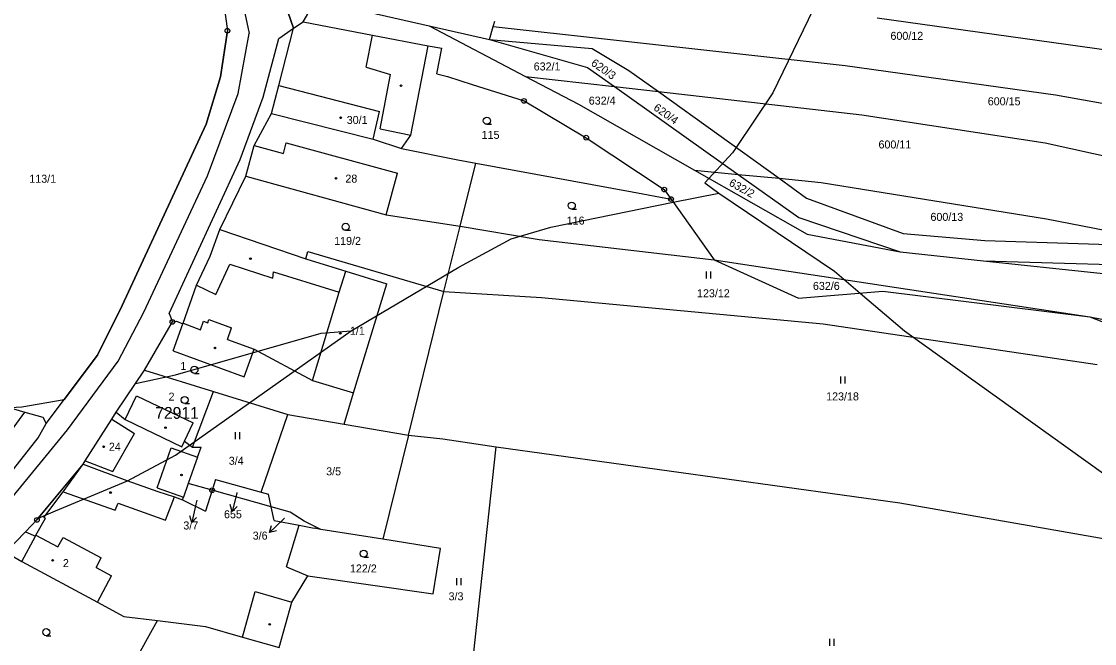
# Model space of a CAD drawing. Extents: x -743888 to -742027, y -1128394 to -1126768.
# Drawn here: x -742825.9 to -742597.9, y -1127325 to -1127193 of the extents above; entities that cross this region are included whole.
import ezdxf

# ---------------------------------------------------------------- set-up
doc = ezdxf.new("R2010")
doc.units = 0
for name, color, linetype in [('Vrstva 1', 7, 'Continuous'), ('Vrstva 16', 7, 'Continuous'), ('Vrstva 18', 7, 'Continuous'), ('Vrstva 19', 7, 'Continuous'), ('Vrstva 24', 7, 'Continuous'), ('Vrstva 25', 7, 'Continuous'), ('Vrstva 3', 7, 'Continuous'), ('Vrstva 37', 7, 'Continuous'), ('Vrstva 4', 7, 'Continuous'), ('Vrstva 52', 7, 'Continuous'), ('Vrstva 53', 7, 'Continuous'), ('Vrstva 6', 7, 'Continuous')]:
    doc.layers.add(name, color=color, linetype=linetype)

msp = doc.modelspace()

# ---------------------------------------------------------------- linework, layer by layer
at = {"layer": 'Vrstva 1'}
for p, q in [((-742743.69, -1127280.81), (-742749.15, -1127302.87)), ((-742788.48, -1127285.47), (-742790.45, -1127291.06)), ((-742790.45, -1127291.06), (-742791.47, -1127293.96)), ((-742785.38, -1127292.47), (-742790.45, -1127291.06)), ((-742772.81, -1127295.97), (-742785.38, -1127292.47)), ((-742768.78, -1127297.1), (-742772.81, -1127295.97)), ((-742765.8, -1127299.02), (-742768.78, -1127297.1)), ((-742762.29, -1127300.78), (-742765.8, -1127299.02)), ((-742762.29, -1127300.78), (-742763.69, -1127300.56)), ((-742749.15, -1127302.87), (-742762.29, -1127300.78)), ((-742736.87, -1127304.83), (-742749.15, -1127302.87))]:
    msp.add_line(p, q, dxfattribs=at)
for points in [[(-742772.5, -1127181.64), (-742768.06, -1127194.37)], [(-742782.95, -1127188.88), (-742782.14, -1127194.94)], [(-742766.04, -1127193.06), (-742763.32, -1127188.38)], [(-742763.32, -1127188.38), (-742739.28, -1127193.88)], [(-742768.06, -1127194.37), (-742766.04, -1127193.06)], [(-742766.04, -1127193.06), (-742751.29, -1127195.85)], [(-742725.69, -1127194.04), (-742725.36, -1127192.86)], [(-742783.62, -1127204.69), (-742782.14, -1127194.94)], [(-742771.21, -1127206.56), (-742768.06, -1127194.37)], [(-742751.29, -1127195.85), (-742739.47, -1127198.11)], [(-742739.28, -1127193.88), (-742726.46, -1127196.81)], [(-742726.46, -1127196.81), (-742725.69, -1127194.04)], [(-742743.16, -1127217.09), (-742739.47, -1127198.11)], [(-742739.47, -1127198.11), (-742736.58, -1127198.66)], [(-742726.46, -1127196.81), (-742705.66, -1127202.71)], [(-742737.64, -1127204.11), (-742736.58, -1127198.66)], [(-742704.64, -1127198.69), (-742696.83, -1127203.36)], [(-742786.61, -1127214.77), (-742783.62, -1127204.69)], [(-742705.66, -1127202.71), (-742699.9, -1127206.79)], [(-742696.83, -1127203.36), (-742690.57, -1127207.86)], [(-742772.74, -1127212.53), (-742771.21, -1127206.56)], [(-742699.9, -1127206.79), (-742673.62, -1127225.43)], [(-742690.57, -1127207.86), (-742664.96, -1127226.26)], [(-742719.13, -1127209.84), (-742705.92, -1127217.63)], [(-742776.45, -1127219.31), (-742772.74, -1127212.53)], [(-742772.74, -1127212.53), (-742751.2, -1127217.94)], [(-742804.45, -1127253.23), (-742786.61, -1127214.77)], [(-742751.2, -1127217.94), (-742745.13, -1127219.95)], [(-742745.13, -1127219.95), (-742743.16, -1127217.09)], [(-742705.92, -1127217.63), (-742689.33, -1127228.64)], [(-742778.23, -1127225.83), (-742776.45, -1127219.31)], [(-742745.13, -1127219.95), (-742733.19, -1127222.32)], [(-742733.19, -1127222.32), (-742729.39, -1127223.02)], [(-742732.7, -1127236.41), (-742729.39, -1127223.02)], [(-742729.39, -1127223.02), (-742696.14, -1127229.14)], [(-742673.62, -1127225.43), (-742660.72, -1127234.58)], [(-742783.76, -1127237.1), (-742778.23, -1127225.83)], [(-742778.23, -1127225.83), (-742748.39, -1127234)], [(-742664.96, -1127226.26), (-742659.14, -1127230.44)], [(-742689.33, -1127228.64), (-742687.9, -1127230.66)], [(-742659.14, -1127230.44), (-742638.6, -1127238)], [(-742748.39, -1127234), (-742732.7, -1127236.41)], [(-742660.72, -1127234.58), (-742639.2, -1127241.9)], [(-742736.14, -1127250.3), (-742732.7, -1127236.41)], [(-742732.7, -1127236.41), (-742715.93, -1127239.23)], [(-742785.8, -1127242.82), (-742783.76, -1127237.1)], [(-742783.76, -1127237.1), (-742765.5, -1127243.32)], [(-742638.6, -1127238), (-742621.26, -1127239.44)], [(-742715.93, -1127239.23), (-742678.76, -1127243.56)], [(-742621.26, -1127239.44), (-742577.19, -1127240.89)], [(-742788.68, -1127248.97), (-742785.8, -1127242.82)], [(-742765.5, -1127243.32), (-742765.02, -1127241.79)], [(-742765.02, -1127241.79), (-742736.14, -1127250.3)], [(-742678.76, -1127243.56), (-742660.81, -1127251.7)], [(-742639.2, -1127241.9), (-742621.56, -1127243.8)], [(-742621.56, -1127243.8), (-742577.26, -1127245.05)], [(-742791.56, -1127257.04), (-742788.68, -1127248.97)], [(-742743.69, -1127280.81), (-742736.14, -1127250.3)], [(-742660.81, -1127251.7), (-742642.9, -1127250.2)], [(-742642.9, -1127250.2), (-742598.97, -1127255.65)], [(-742809.73, -1127263.8), (-742804.45, -1127253.23)], [(-742799.73, -1127266.98), (-742793.82, -1127256.75)], [(-742793.82, -1127256.75), (-742793.38, -1127256.68)], [(-742793.68, -1127262.86), (-742791.59, -1127257.13)], [(-742793.38, -1127256.68), (-742792.94, -1127256.6)], [(-742792.94, -1127256.6), (-742791.59, -1127257.13)], [(-742791.59, -1127257.13), (-742791.56, -1127257.04)], [(-742598.97, -1127255.65), (-742576.72, -1127264.27)], [(-742820.62, -1127278.32), (-742809.73, -1127263.8)], [(-742793.68, -1127262.86), (-742778.58, -1127268.39)], [(-742778.58, -1127268.39), (-742776.45, -1127262.56)], [(-742776.45, -1127262.56), (-742764.09, -1127269.15)], [(-742805.74, -1127275.9), (-742799.73, -1127266.98)], [(-742799.73, -1127266.98), (-742785.11, -1127271.49)], [(-742764.09, -1127269.15), (-742755.34, -1127271.83)], [(-742803.83, -1127277.46), (-742801.41, -1127272.41)], [(-742801.41, -1127272.41), (-742789.37, -1127278.2)], [(-742785.11, -1127271.49), (-742769.26, -1127276.37)], [(-742757.36, -1127278.44), (-742755.34, -1127271.83)], [(-742829.13, -1127281.34), (-742825.16, -1127275.88)], [(-742821.32, -1127276.99), (-742820.62, -1127278.32)], [(-742812.31, -1127286.21), (-742806.68, -1127277.37)], [(-742806.68, -1127277.37), (-742805.74, -1127275.9)], [(-742805.74, -1127275.9), (-742803.83, -1127277.46)], [(-742774.96, -1127292.87), (-742769.26, -1127276.37)], [(-742769.26, -1127276.37), (-742757.36, -1127278.44)], [(-742822.34, -1127281.33), (-742820.62, -1127278.32)], [(-742791.23, -1127282.07), (-742789.37, -1127278.2)], [(-742757.36, -1127278.44), (-742743.69, -1127280.81)], [(-742831.45, -1127292.86), (-742822.34, -1127281.33)], [(-742791.23, -1127282.07), (-742789.51, -1127283.3)], [(-742789.51, -1127283.3), (-742787.73, -1127283.35)], [(-742788.48, -1127285.47), (-742787.73, -1127283.35)], [(-742822.58, -1127298.79), (-742812.76, -1127286.93)], [(-742812.76, -1127286.93), (-742812.31, -1127286.21)], [(-742812.76, -1127286.93), (-742803.47, -1127290.41)], [(-742803.47, -1127290.41), (-742796.91, -1127292.72)], [(-742796.91, -1127292.72), (-742793.35, -1127293.9)], [(-742793.35, -1127293.9), (-742791.67, -1127294.54)], [(-742791.67, -1127294.54), (-742791.47, -1127293.96)], [(-742825.03, -1127301.3), (-742822.58, -1127298.79)], [(-742769.57, -1127308.75), (-742766.91, -1127299.92)], [(-742766.91, -1127299.92), (-742763.69, -1127300.56)], [(-742829.22, -1127305.6), (-742825.03, -1127301.3)], [(-742825.81, -1127307.59), (-742822.92, -1127302.22)], [(-742825.03, -1127301.3), (-742822.92, -1127302.22)], [(-742738.41, -1127314.45), (-742736.87, -1127304.83)], [(-742825.81, -1127307.59), (-742809.73, -1127316.24)], [(-742769.57, -1127308.75), (-742765.04, -1127310.66)], [(-742768.44, -1127316.21), (-742765.04, -1127310.66)], [(-742765.04, -1127310.66), (-742738.41, -1127314.45)], [(-742809.73, -1127316.24), (-742804.13, -1127319.29)], [(-742771.16, -1127325.84), (-742768.44, -1127316.21)], [(-742808.12, -1127340.19), (-742796.97, -1127320.16)], [(-742804.13, -1127319.29), (-742796.97, -1127320.16)], [(-742796.97, -1127320.16), (-742786.76, -1127321.38)], [(-742786.76, -1127321.38), (-742778.95, -1127323.64)], [(-742778.95, -1127323.64), (-742771.16, -1127325.84)]]:
    msp.add_lwpolyline(points, dxfattribs=at)
at = {"layer": 'Vrstva 16'}
for p, q in [((-742780.06, -1127295.9), (-742781.1, -1127296.98)), ((-742788.68, -1127298.25), (-742789.7, -1127299.35)), ((-742771.72, -1127301.08), (-742773.18, -1127301.43))]:
    msp.add_line(p, q, dxfattribs=at)
for points in [[(-742780.13, -1127293.1), (-742781.1, -1127296.98), (-742781.51, -1127295.54)], [(-742780.11, -1127292.99), (-742780.13, -1127293.1)], [(-742788.81, -1127295.45), (-742789.7, -1127299.35), (-742790.14, -1127297.91)], [(-742788.62, -1127294.6), (-742788.81, -1127295.45)], [(-742769.98, -1127298.38), (-742770.29, -1127298.67)], [(-742770.29, -1127298.67), (-742773.18, -1127301.43), (-742772.76, -1127299.99)]]:
    msp.add_lwpolyline(points, dxfattribs=at)
at = {"layer": 'Vrstva 24'}
for p, q in [((-742782.19, -1127194.94), (-742782.09, -1127194.94)), ((-742719.18, -1127209.84), (-742719.08, -1127209.84)), ((-742705.97, -1127217.63), (-742705.87, -1127217.63)), ((-742689.38, -1127228.64), (-742689.28, -1127228.64)), ((-742687.95, -1127230.66), (-742687.85, -1127230.66)), ((-742793.87, -1127256.75), (-742793.77, -1127256.75)), ((-742785.43, -1127292.47), (-742785.33, -1127292.47)), ((-742822.63, -1127298.79), (-742822.53, -1127298.79))]:
    msp.add_line(p, q, dxfattribs=at)
for centre in [(-742782.14, -1127194.94), (-742719.13, -1127209.84), (-742705.92, -1127217.63), (-742689.33, -1127228.64), (-742687.9, -1127230.66), (-742793.82, -1127256.75), (-742785.38, -1127292.47), (-742822.58, -1127298.79)]:
    msp.add_circle(centre, 0.499, dxfattribs=at)
at = {"layer": 'Vrstva 25'}
for p, q in [((-742727.02, -1127214.79), (-742726.02, -1127214.79)), ((-742708.98, -1127232.8), (-742707.98, -1127232.8)), ((-742757.01, -1127237.29), (-742756.01, -1127237.29)), ((-742680.46, -1127246.03), (-742680.46, -1127247.53)), ((-742679.46, -1127247.53), (-742679.46, -1127246.03)), ((-742789.13, -1127267.66), (-742788.13, -1127267.66)), ((-742651.92, -1127268.35), (-742651.92, -1127269.85)), ((-742650.92, -1127269.85), (-742650.92, -1127268.35)), ((-742791.2, -1127274.07), (-742790.2, -1127274.07)), ((-742780.5, -1127280.17), (-742780.5, -1127281.67)), ((-742779.5, -1127281.67), (-742779.5, -1127280.17)), ((-742753.17, -1127306.69), (-742752.17, -1127306.69)), ((-742733.47, -1127311.15), (-742733.47, -1127312.65)), ((-742732.47, -1127312.65), (-742732.47, -1127311.15)), ((-742820.6, -1127323.36), (-742819.6, -1127323.36)), ((-742654.24, -1127324.03), (-742654.24, -1127325.53)), ((-742653.24, -1127325.53), (-742653.24, -1127324.03))]:
    msp.add_line(p, q, dxfattribs=at)
for centre, radius in [((-742745.24, -1127206.6), 0.175), ((-742758.08, -1127213.41), 0.175), ((-742727.02, -1127214.04), 0.75), ((-742759.05, -1127226.26), 0.175), ((-742708.98, -1127232.05), 0.75), ((-742757.01, -1127236.54), 0.75), ((-742777.23, -1127243.3), 0.175), ((-742758.15, -1127259.17), 0.175), ((-742784.77, -1127262.27), 0.175), ((-742789.13, -1127266.91), 0.75), ((-742791.2, -1127273.32), 0.75), ((-742795.28, -1127279.21), 0.175), ((-742808.43, -1127283.25), 0.175), ((-742791.88, -1127289.26), 0.175), ((-742806.95, -1127292.97), 0.175), ((-742753.17, -1127305.94), 0.75), ((-742819.26, -1127307.37), 0.175), ((-742773.15, -1127320.95), 0.175), ((-742820.6, -1127322.61), 0.75)]:
    msp.add_circle(centre, radius, dxfattribs=at)
at = {"layer": 'Vrstva 3'}
for points in [[(-742772.74, -1127212.53), (-742771.21, -1127206.56)], [(-742771.21, -1127206.56), (-742749.8, -1127212.05)], [(-742772.74, -1127212.53), (-742751.2, -1127217.94)], [(-742751.2, -1127217.94), (-742749.8, -1127212.05)], [(-742778.23, -1127225.83), (-742776.45, -1127219.31)], [(-742776.45, -1127219.31), (-742770.25, -1127221)], [(-742770.25, -1127221), (-742769.62, -1127218.71)], [(-742769.62, -1127218.71), (-742745.98, -1127225.18)], [(-742748.39, -1127234), (-742745.98, -1127225.18)], [(-742778.23, -1127225.83), (-742748.39, -1127234)], [(-742758.36, -1127250.41), (-742757, -1127245.96)], [(-742757, -1127245.96), (-742748.25, -1127248.63)], [(-742764.09, -1127269.15), (-742758.36, -1127250.41)], [(-742755.34, -1127271.83), (-742748.25, -1127248.63)], [(-742764.09, -1127269.15), (-742755.34, -1127271.83)], [(-742812.31, -1127286.21), (-742806.68, -1127277.37)], [(-742806.68, -1127277.37), (-742801.85, -1127280.44)], [(-742806.5, -1127288.47), (-742801.85, -1127280.44)], [(-742812.31, -1127286.21), (-742806.5, -1127288.47)], [(-742825.81, -1127307.59), (-742822.92, -1127302.22)], [(-742822.92, -1127302.22), (-742822.8, -1127302)], [(-742822.8, -1127302), (-742818.13, -1127304.52)], [(-742818.13, -1127304.52), (-742817.03, -1127302.49)], [(-742817.03, -1127302.49), (-742808.92, -1127306.85)], [(-742810.01, -1127308.88), (-742808.92, -1127306.85)], [(-742825.81, -1127307.59), (-742809.73, -1127316.24)], [(-742810.01, -1127308.88), (-742806.73, -1127310.65)], [(-742809.73, -1127316.24), (-742806.73, -1127310.65)]]:
    msp.add_lwpolyline(points, dxfattribs=at)
at = {"layer": 'Vrstva 37'}
for centre in [(-742758.08, -1127213.41), (-742759.05, -1127226.26), (-742758.15, -1127259.17), (-742808.43, -1127283.25), (-742819.26, -1127307.37)]:
    msp.add_circle(centre, 0.175, dxfattribs=at)
at = {"layer": 'Vrstva 4'}
for points in [[(-742779.59, -1127185.83), (-742777.49, -1127195.5)], [(-742779.83, -1127208.27), (-742777.49, -1127195.5)], [(-742771.22, -1127196.55), (-742768.06, -1127194.37)], [(-742752.68, -1127202.66), (-742751.29, -1127195.85)], [(-742774.52, -1127209.02), (-742771.22, -1127196.55)], [(-742752.68, -1127202.66), (-742747.52, -1127204.24)], [(-742749.65, -1127215.74), (-742747.52, -1127204.24)], [(-742771.21, -1127206.56), (-742749.8, -1127212.05)], [(-742786.33, -1127225.73), (-742779.83, -1127208.27)], [(-742779.4, -1127222.27), (-742774.52, -1127209.02)], [(-742751.2, -1127217.94), (-742749.8, -1127212.05)], [(-742749.65, -1127215.74), (-742743.16, -1127217.09)], [(-742776.45, -1127219.31), (-742770.25, -1127221)], [(-742770.25, -1127221), (-742769.62, -1127218.71)], [(-742769.62, -1127218.71), (-742745.98, -1127225.18)], [(-742794.47, -1127254.98), (-742779.4, -1127222.27)], [(-742748.39, -1127234), (-742745.98, -1127225.18)], [(-742799.87, -1127254.66), (-742786.33, -1127225.73)], [(-742765.5, -1127243.32), (-742757.86, -1127245.7)], [(-742784.62, -1127250.9), (-742781.6, -1127244.46)], [(-742781.6, -1127244.46), (-742772.5, -1127247.48)], [(-742758.36, -1127250.41), (-742757, -1127245.96)], [(-742757.86, -1127245.7), (-742757, -1127245.96)], [(-742757, -1127245.96), (-742748.25, -1127248.63)], [(-742772.5, -1127247.48), (-742772.35, -1127246.12)], [(-742772.35, -1127246.12), (-742759.55, -1127250.04)], [(-742788.68, -1127248.97), (-742784.62, -1127250.9)], [(-742764.09, -1127269.15), (-742758.36, -1127250.41)], [(-742759.55, -1127250.04), (-742758.36, -1127250.41)], [(-742755.34, -1127271.83), (-742748.25, -1127248.63)], [(-742805.34, -1127265.1), (-742799.87, -1127254.66)], [(-742794.47, -1127254.98), (-742793.82, -1127256.75)], [(-742791.56, -1127257.04), (-742787.87, -1127258.39)], [(-742787.87, -1127258.39), (-742787.22, -1127256.6)], [(-742787.22, -1127256.6), (-742786.32, -1127256.93)], [(-742786.32, -1127256.93), (-742786.08, -1127256.25)], [(-742786.08, -1127256.25), (-742781.24, -1127258.02)], [(-742782.14, -1127260.48), (-742781.24, -1127258.02)], [(-742782.14, -1127260.48), (-742776.45, -1127262.56)], [(-742816.12, -1127279.67), (-742805.34, -1127265.1)], [(-742806.68, -1127277.37), (-742801.85, -1127280.44)], [(-742803.83, -1127277.46), (-742791.8, -1127283.24)], [(-742828.54, -1127294.89), (-742816.12, -1127279.67)], [(-742806.5, -1127288.47), (-742801.85, -1127280.44)], [(-742791.8, -1127283.24), (-742791.23, -1127282.07)], [(-742797.08, -1127291.98), (-742794.09, -1127283.5)], [(-742794.09, -1127283.5), (-742788.48, -1127285.47)], [(-742817.01, -1127292.85), (-742812.76, -1127286.93)], [(-742812.31, -1127286.21), (-742806.5, -1127288.47)], [(-742821.15, -1127298.28), (-742817.01, -1127292.85)], [(-742817.01, -1127292.85), (-742805.94, -1127296.71)], [(-742797.08, -1127291.98), (-742791.47, -1127293.96)], [(-742805.94, -1127296.71), (-742805.36, -1127295.2)], [(-742805.36, -1127295.2), (-742795.29, -1127298.83)], [(-742795.29, -1127298.83), (-742793.35, -1127293.9)], [(-742821.15, -1127298.28), (-742820.79, -1127298.44)], [(-742822.8, -1127302), (-742820.79, -1127298.44)], [(-742822.92, -1127302.22), (-742822.8, -1127302)], [(-742822.8, -1127302), (-742818.13, -1127304.52)], [(-742818.13, -1127304.52), (-742817.03, -1127302.49)], [(-742817.03, -1127302.49), (-742808.92, -1127306.85)], [(-742829.22, -1127305.6), (-742825.81, -1127307.59)], [(-742810.01, -1127308.88), (-742808.92, -1127306.85)], [(-742810.01, -1127308.88), (-742806.73, -1127310.65)], [(-742809.73, -1127316.24), (-742806.73, -1127310.65)], [(-742778.95, -1127323.64), (-742776.23, -1127314.01)], [(-742776.23, -1127314.01), (-742768.44, -1127316.21)]]:
    msp.add_lwpolyline(points, dxfattribs=at)
at = {"layer": 'Vrstva 52'}
for points in [[(-742646.81, -1127076.25), (-742640.88, -1127093.63), (-742639.56, -1127114), (-742642.13, -1127136.88), (-742643.44, -1127139.5), (-742645.13, -1127154.75), (-742647.25, -1127164.88), (-742654.44, -1127183.63), (-742666.31, -1127208.13), (-742674.05, -1127219.73), (-742674.81, -1127220.88), (-742680.75, -1127227.25), (-742677.75, -1127229.38)], [(-743021.39, -1127124.08), (-742966.69, -1127134.89), (-742939.19, -1127141.02), (-742879.66, -1127154.29), (-742876.73, -1127154.94), (-742831.39, -1127163.51), (-742830.93, -1127163.61), (-742806.35, -1127169.04), (-742795.67, -1127173.47), (-742787.26, -1127180.14), (-742783.29, -1127187.16), (-742782.95, -1127188.88), (-742782.14, -1127194.94), (-742783.62, -1127204.69), (-742786.61, -1127214.77), (-742804.45, -1127253.23), (-742809.73, -1127263.8), (-742816.8, -1127273.23)], [(-742801.66, -1127269.85), (-742799.73, -1127266.98), (-742793.82, -1127256.75), (-742793.38, -1127256.68), (-742792.94, -1127256.6), (-742791.59, -1127257.13), (-742791.56, -1127257.04), (-742788.68, -1127248.97), (-742785.8, -1127242.82), (-742783.76, -1127237.1), (-742778.23, -1127225.83), (-742776.45, -1127219.31), (-742772.74, -1127212.53), (-742771.21, -1127206.56), (-742768.06, -1127194.37), (-742772.5, -1127181.64), (-742781.25, -1127169.22), (-742796.14, -1127160.57), (-742813.25, -1127156.61), (-742828.27, -1127153.14)], [(-742755.81, -1127258.63), (-742732.94, -1127245.13), (-742721.88, -1127239.13), (-742713.44, -1127236.63), (-742687.42, -1127231.34), (-742677.75, -1127229.38)], [(-742677.75, -1127229.38), (-742653.19, -1127246), (-742647.76, -1127250.61), (-742638.31, -1127258.63), (-742572.56, -1127305.75), (-742545.81, -1127321), (-742506.38, -1127341.38)], [(-743005.69, -1127233.63), (-742969.63, -1127243.88), (-742962.88, -1127246.75), (-742919.65, -1127262.15), (-742916.59, -1127263.24), (-742910.25, -1127265.5), (-742873.38, -1127274.38), (-742864.88, -1127276), (-742846.63, -1127276), (-742825.81, -1127274.75), (-742816.8, -1127273.23)], [(-742822.26, -1127298.41), (-742818.63, -1127296.88), (-742803.38, -1127290.5), (-742793.19, -1127285), (-742755.81, -1127258.63)], [(-742801.66, -1127269.85), (-742793.19, -1127268), (-742762.19, -1127259.13), (-742755.81, -1127258.63)], [(-742822.26, -1127298.41), (-742812.76, -1127286.93), (-742812.31, -1127286.21), (-742806.68, -1127277.37), (-742805.74, -1127275.9), (-742801.66, -1127269.85)], [(-742842.71, -1127304.28), (-742831.45, -1127292.86), (-742822.34, -1127281.33), (-742820.62, -1127278.32), (-742816.8, -1127273.23)], [(-742848.82, -1127325.8), (-742829.22, -1127305.6), (-742825.03, -1127301.3), (-742822.58, -1127298.79), (-742822.26, -1127298.41)]]:
    msp.add_lwpolyline(points, dxfattribs=at)
at = {"layer": 'Vrstva 6'}
for points in [[(-742644.1, -1127192.22), (-742566.48, -1127203.04)], [(-742739.28, -1127193.88), (-742718.84, -1127204.63)], [(-742725.69, -1127194.04), (-742650.94, -1127202.29)], [(-742726.46, -1127196.81), (-742704.64, -1127198.69)], [(-742650.94, -1127202.29), (-742606.23, -1127208.56)], [(-742737.64, -1127204.11), (-742735.37, -1127204.64)], [(-742735.37, -1127204.64), (-742730.16, -1127206.35)], [(-742718.84, -1127204.63), (-742699.9, -1127206.79)], [(-742718.84, -1127204.63), (-742707.57, -1127210.55)], [(-742730.16, -1127206.35), (-742719.13, -1127209.84)], [(-742699.9, -1127206.79), (-742690.57, -1127207.86)], [(-742690.57, -1127207.86), (-742647.39, -1127212.79)], [(-742606.23, -1127208.56), (-742569.32, -1127215.09)], [(-742707.57, -1127210.55), (-742682.93, -1127224.54)], [(-742647.39, -1127212.79), (-742608.43, -1127218.73)], [(-742608.43, -1127218.73), (-742572.17, -1127226.73)], [(-742682.93, -1127224.54), (-742658.99, -1127238.12)], [(-742682.93, -1127224.54), (-742673.62, -1127225.43)], [(-742673.62, -1127225.43), (-742664.96, -1127226.26)], [(-742664.96, -1127226.26), (-742655.98, -1127227.12)], [(-742655.98, -1127227.12), (-742608.13, -1127234.85)], [(-742696.14, -1127229.14), (-742687.9, -1127230.66)], [(-742687.9, -1127230.66), (-742678.76, -1127243.56)], [(-742608.13, -1127234.85), (-742577.19, -1127240.89)], [(-742658.99, -1127238.12), (-742639.2, -1127241.9)], [(-742678.76, -1127243.56), (-742598.97, -1127255.65)], [(-742621.56, -1127243.8), (-742574.02, -1127248.78)], [(-742736.14, -1127250.3), (-742715.39, -1127251.55)], [(-742715.39, -1127251.55), (-742655.59, -1127257.18)], [(-742655.59, -1127257.18), (-742597.39, -1127265.81)], [(-742598.97, -1127255.65), (-742576.08, -1127260.13)], [(-742789.51, -1127283.3), (-742785.11, -1127271.49)], [(-742828.77, -1127274.84), (-742825.16, -1127275.88)], [(-742825.16, -1127275.88), (-742821.32, -1127276.99)], [(-742743.69, -1127280.81), (-742736.37, -1127281.56)], [(-742736.37, -1127281.56), (-742725.03, -1127283.28)], [(-742731.72, -1127344.4), (-742725.03, -1127283.28)], [(-742725.03, -1127283.28), (-742639.33, -1127295.15)], [(-742784.67, -1127290.21), (-742785.38, -1127292.47)], [(-742784.67, -1127290.21), (-742774.96, -1127292.87)], [(-742785.38, -1127292.47), (-742786.8, -1127296.94)], [(-742774.96, -1127292.87), (-742773.39, -1127293.3)], [(-742772.81, -1127295.97), (-742773.39, -1127293.3)], [(-742791.67, -1127294.54), (-742786.8, -1127296.94)], [(-742772.19, -1127298.87), (-742772.81, -1127295.97)], [(-742639.33, -1127295.15), (-742583.12, -1127305.02)], [(-742772.19, -1127298.87), (-742766.91, -1127299.92)]]:
    msp.add_lwpolyline(points, dxfattribs=at)

# ---------------------------------------------------------------- texts
at = {"layer": 'Vrstva 16'}
for s, p in [('655', (-742782.85, -1127298.43)), ('3/7', (-742791.49, -1127300.81)), ('3/6', (-742776.76, -1127302.96))]:
    msp.add_text(s, height=1.7, dxfattribs=at).set_placement(p)
at = {"layer": 'Vrstva 18'}
for s, height, p in [('600/12', 1.7, (-742641.29, -1127196.86)), ('632/1', 1.7, (-742717.07, -1127203.36)), ('632/4', 1.7, (-742705.38, -1127210.61)), ('600/15', 1.7, (-742620.62, -1127210.76)), ('115', 1.7, (-742728.12, -1127217.88)), ('600/11', 1.7, (-742643.83, -1127219.92)), ('113/1', 1.7, (-742824.2, -1127227.2)), ('116', 1.7, (-742710.06, -1127236.08)), ('600/13', 1.7, (-742632.79, -1127235.3)), ('119/2', 1.7, (-742759.45, -1127240.4)), ('632/6', 1.7, (-742657.76, -1127249.95)), ('123/12', 1.7, (-742682.38, -1127251.51)), ('1', 1.7, (-742792.12, -1127266.95)), ('2', 1.7, (-742794.63, -1127273.46)), ('123/18', 1.7, (-742654.95, -1127273.41)), ('3/4', 1.7, (-742781.84, -1127287.07)), ('3/5', 1.7, (-742761.15, -1127289.32)), ('655', 0.1, (-742780.11, -1127292.99)), ('3/7', 0.1, (-742788.62, -1127294.6)), ('3/6', 0.1, (-742769.98, -1127298.38)), ('122/2', 1.7, (-742756.1, -1127309.94)), ('3/3', 1.7, (-742735.15, -1127315.85))]:
    msp.add_text(s, height=height, dxfattribs=at).set_placement(p)
for s, rotation, p in [('620/3', 324.9771, (-742705.04, -1127202.14)), ('620/4', 324.3932, (-742691.77, -1127211.61)), ('632/2', 331.0561, (-742675.75, -1127227.71))]:
    msp.add_text(s, height=1.7, rotation=rotation, dxfattribs=at).set_placement(p)
at = {"layer": 'Vrstva 19'}
for s, p in [('30/1', (-742756.78, -1127214.72)), ('28', (-742757.07, -1127227.17)), ('1/1', (-742756.11, -1127259.47)), ('24', (-742807.3, -1127284.09)), ('2', (-742817.07, -1127308.8))]:
    msp.add_text(s, height=1.7, dxfattribs=at).set_placement(p)
at = {"layer": 'Vrstva 53'}
msp.add_text('72911', height=2.5, dxfattribs=at).set_placement((-742797.48, -1127277.31))

doc.saveas('drawing.dxf')
